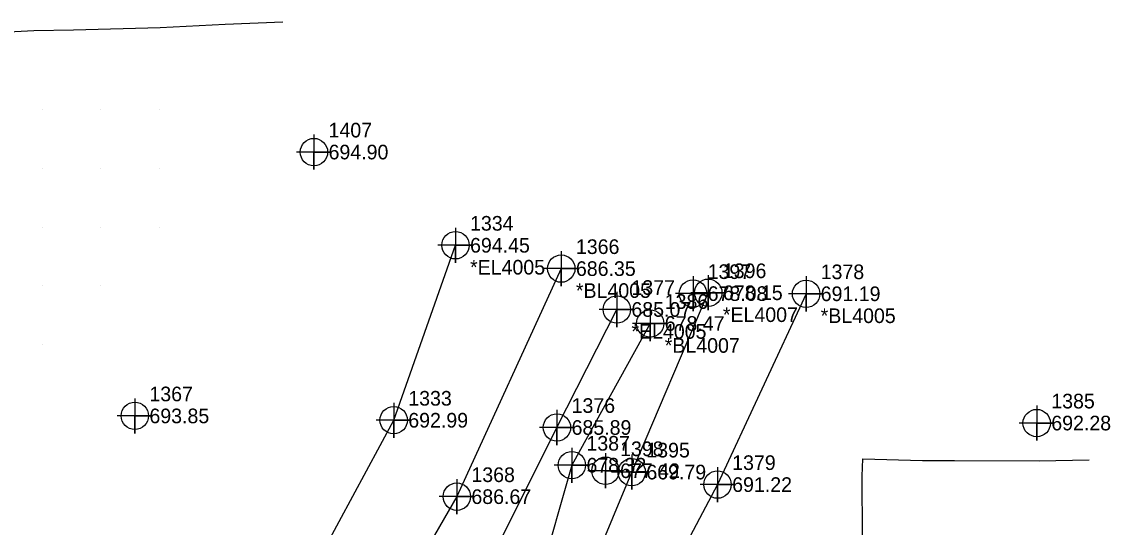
# Model space of a CAD drawing. Extents: x 1755643 to 1760494, y 736519 to 737621.
# Drawn here: x 1759022 to 1759208.1, y 737123.7 to 737210.1 of the extents above; entities that cross this region are included whole.
import ezdxf

# ---------------------------------------------------------------- set-up
doc = ezdxf.new("R2010")
doc.units = 0
for name, color, linetype in [('Exist Horizontal Alignment Curve and Spiral Data', 7, 'Continuous'), ('Exist Horizontal Alignment Direction Label', 7, 'Continuous'), ('Exist Railroads Standard Gauge', 7, 'Continuous'), ('Exist Roads EOT', 7, 'Continuous'), ('Exist Utilities Sanitary Sewer UG Line', 7, 'Continuous'), ('Old_Level_3', 7, 'Continuous'), ('Prop Conc 5in Monolithic Keyed In Island', 7, 'Continuous'), ('Prop EOT Dash', 7, 'Continuous'), ('Prop Horizontal Alignment Station Label', 7, 'Continuous'), ('Prop Horizontal Alignment Tick Label', 7, 'Continuous'), ('Prop Horizontal Alignment Tick Large', 7, 'Continuous'), ('Prop Horizontal Alignment Tick Small', 7, 'Continuous'), ('Prop Lane Lines', 7, 'Continuous'), ('Prop Paint Stripe', 7, 'Continuous'), ('Prop Paved Shoulder', 7, 'Continuous'), ('Prop Superelevation Label', 7, 'Continuous'), ('Prop Terminator CELL', 7, 'Continuous'), ('Scratch_Level_9', 7, 'Continuous')]:
    doc.layers.add(name, color=color, linetype=linetype)

msp = doc.modelspace()

# ---------------------------------------------------------------- linework, layer by layer
at = {"layer": 'Exist Horizontal Alignment Curve and Spiral Data'}
for points in [[(1759071.95, 737190.81), (1759071.95, 737184.81), (1759071.95, 737187.81), (1759074.95, 737187.81), (1759068.95, 737187.81)], [(1759041.32, 737145.72), (1759041.32, 737139.72), (1759041.32, 737142.72), (1759044.32, 737142.72), (1759038.32, 737142.72)], [(1759195.52, 737144.5), (1759195.52, 737138.5), (1759195.52, 737141.5), (1759198.52, 737141.5), (1759192.52, 737141.5)]]:
    msp.add_lwpolyline(points, dxfattribs=at)
for centre in [(1759071.95, 737187.81), (1759041.32, 737142.72), (1759195.52, 737141.5)]:
    msp.add_circle(centre, 2.34, dxfattribs=at)
at = {"layer": 'Exist Railroads Standard Gauge'}
for points in [[(1758963.25, 737206.56), (1758981.75, 737206.72), (1758990.89, 737207.08), (1759006.59, 737207.68), (1759024.04, 737208.6), (1759030.84, 737208.71), (1759045.64, 737209.09), (1759056.75, 737209.66), (1759066.65, 737210.07)], [(1759166.23, 737089.04), (1759166.56, 737104.02), (1759165.73, 737122.15), (1759165.69, 737132.45), (1759165.81, 737135.36), (1759176, 737135.12), (1759181.45, 737135.1), (1759195.95, 737135.05), (1759204.48, 737135.24)]]:
    msp.add_lwpolyline(points, dxfattribs=at)
at = {"layer": 'Prop Horizontal Alignment Station Label'}
for points in [[(1759136.76, 737166.62), (1759136.76, 737160.62), (1759136.76, 737163.62), (1759139.76, 737163.62), (1759133.76, 737163.62)], [(1759121.79, 737136.35), (1759121.79, 737130.35), (1759121.79, 737133.35), (1759124.79, 737133.35), (1759118.79, 737133.35)]]:
    msp.add_lwpolyline(points, dxfattribs=at)
for centre in [(1759136.76, 737163.62), (1759121.79, 737133.35)]:
    msp.add_circle(centre, 2.34, dxfattribs=at)
at = {"layer": 'Prop Horizontal Alignment Tick Small'}
for points in [[(1759139.37, 737166.77), (1759139.37, 737160.77), (1759139.37, 737163.77), (1759142.37, 737163.77), (1759136.37, 737163.77)], [(1759129.43, 737161.51), (1759129.43, 737155.51), (1759129.43, 737158.51), (1759132.43, 737158.51), (1759126.43, 737158.51)], [(1759116.04, 737137.29), (1759116.04, 737131.29), (1759116.04, 737134.29), (1759119.04, 737134.29), (1759113.04, 737134.29)], [(1759126.28, 737136.12), (1759126.28, 737130.12), (1759126.28, 737133.12), (1759129.28, 737133.12), (1759123.28, 737133.12)]]:
    msp.add_lwpolyline(points, dxfattribs=at)
for centre in [(1759139.37, 737163.77), (1759129.43, 737158.51), (1759116.04, 737134.29), (1759126.28, 737133.12)]:
    msp.add_circle(centre, 2.34, dxfattribs=at)
at = {"layer": 'Prop Lane Lines'}
for points in [[(1759096.14, 737174.88), (1759096.14, 737168.88), (1759096.14, 737171.88), (1759099.14, 737171.88), (1759093.14, 737171.88)], [(1759114.24, 737170.89), (1759114.24, 737164.89), (1759114.24, 737167.89), (1759117.24, 737167.89), (1759111.24, 737167.89)], [(1759156.09, 737166.59), (1759156.09, 737160.59), (1759156.09, 737163.59), (1759159.09, 737163.59), (1759153.09, 737163.59)], [(1759123.73, 737163.9), (1759123.73, 737157.9), (1759123.73, 737160.9), (1759126.73, 737160.9), (1759120.73, 737160.9)], [(1759085.58, 737144.98), (1759085.58, 737138.98), (1759085.58, 737141.98), (1759088.58, 737141.98), (1759082.58, 737141.98)], [(1759113.5, 737143.74), (1759113.5, 737137.74), (1759113.5, 737140.74), (1759116.5, 737140.74), (1759110.5, 737140.74)], [(1759140.96, 737133.98), (1759140.96, 737127.98), (1759140.96, 737130.98), (1759143.96, 737130.98), (1759137.96, 737130.98)], [(1759096.37, 737131.92), (1759096.37, 737125.92), (1759096.37, 737128.92), (1759099.37, 737128.92), (1759093.37, 737128.92)]]:
    msp.add_lwpolyline(points, dxfattribs=at)
for centre in [(1759096.14, 737171.88), (1759114.24, 737167.89), (1759156.09, 737163.59), (1759123.73, 737160.9), (1759085.58, 737141.98), (1759113.5, 737140.74), (1759140.96, 737130.98), (1759096.37, 737128.92)]:
    msp.add_circle(centre, 2.34, dxfattribs=at)
at = {"layer": 'Prop Paint Stripe'}
for p, q in [((1759025.51, 737195.01), (1759025.51, 737195.01)), ((1759035.51, 737195.01), (1759035.51, 737195.01)), ((1759045.51, 737195.01), (1759045.51, 737195.01)), ((1759025.51, 737185), (1759025.51, 737185)), ((1759035.51, 737185), (1759035.51, 737185)), ((1759045.51, 737185), (1759045.51, 737185)), ((1759025.51, 737175), (1759025.51, 737175)), ((1759035.51, 737175), (1759035.51, 737175)), ((1759045.51, 737175), (1759045.51, 737175)), ((1759025.51, 737165), (1759025.51, 737165)), ((1759035.51, 737165), (1759035.51, 737165)), ((1759025.51, 737155), (1759025.51, 737155)), ((1759205.53, 737145), (1759205.53, 737145))]:
    msp.add_line(p, q, dxfattribs=at)
at = {"layer": 'Prop Terminator CELL'}
for points in [[(1759091.13, 737054.23), (1759095.9, 737066.78), (1759106.11, 737092.63), (1759116.26, 737109.01), (1759126.28, 737133.12), (1759139.37, 737163.77)], [(1759129.43, 737158.51), (1759116.04, 737134.29), (1759110.5, 737114.91), (1759098.55, 737092.32), (1759085.82, 737054.03)]]:
    msp.add_lwpolyline(points, dxfattribs=at)
at = {"layer": 'Scratch_Level_9'}
for points in [[(1759028.25, 737064.28), (1759045.7, 737067.65), (1759061.18, 737092.69), (1759069.23, 737111.66), (1759085.58, 737141.98), (1759096.14, 737171.88)], [(1759114.24, 737167.89), (1759096.37, 737128.92), (1759076.67, 737094.82), (1759063.37, 737070.55), (1759053.4, 737057.9), (1759070.29, 737057.83), (1759078.13, 737065.6), (1759087.49, 737092.17), (1759101.52, 737116.77), (1759113.5, 737140.74), (1759123.73, 737160.9)], [(1759156.09, 737163.59), (1759140.96, 737130.98), (1759127.5, 737105.58), (1759120.62, 737081.6), (1759120.42, 737066.39), (1759121.45, 737059.32)]]:
    msp.add_lwpolyline(points, dxfattribs=at)

# ---------------------------------------------------------------- texts
at = {"layer": 'Exist Horizontal Alignment Direction Label'}
for s, p in [('*EL4005', (1759098.64, 737166.88)), ('*BL4005', (1759116.74, 737162.89)), ('*BL4005', (1759158.59, 737158.59)), ('*EL4005', (1759126.23, 737155.91))]:
    msp.add_text(s, height=2.5, dxfattribs=at).set_placement(p)
at = {"layer": 'Exist Roads EOT'}
for s, p in [('1407', (1759074.45, 737190.31)), ('1367', (1759043.82, 737145.22)), ('1385', (1759198.02, 737144))]:
    msp.add_text(s, height=2.5, dxfattribs=at).set_placement(p)
at = {"layer": 'Exist Utilities Sanitary Sewer UG Line'}
for s, p in [('678.15', (1759141.87, 737162.52)), ('678.47', (1759131.93, 737157.26)), ('678.32', (1759118.54, 737133.04)), ('669.79', (1759128.78, 737131.87))]:
    msp.add_text(s, height=2.5, dxfattribs=at).set_placement(p)
at = {"layer": 'Old_Level_3'}
for s, p in [('694.45', (1759098.64, 737170.63)), ('686.35', (1759116.74, 737166.64)), ('691.19', (1759158.59, 737162.34)), ('685.07', (1759126.23, 737159.66)), ('692.99', (1759088.08, 737140.73)), ('685.89', (1759116, 737139.49)), ('691.22', (1759143.46, 737129.73)), ('686.67', (1759098.87, 737127.67))]:
    msp.add_text(s, height=2.5, dxfattribs=at).set_placement(p)
at = {"layer": 'Prop Conc 5in Monolithic Keyed In Island'}
for s, p in [('1396', (1759141.87, 737166.27)), ('1386', (1759131.93, 737161.01)), ('1387', (1759118.54, 737136.79)), ('1395', (1759128.78, 737135.62))]:
    msp.add_text(s, height=2.5, dxfattribs=at).set_placement(p)
at = {"layer": 'Prop EOT Dash'}
for s, p in [('1334', (1759098.64, 737174.38)), ('1366', (1759116.74, 737170.39)), ('1378', (1759158.59, 737166.09)), ('1377', (1759126.23, 737163.41)), ('1333', (1759088.08, 737144.48)), ('1376', (1759116, 737143.24)), ('1379', (1759143.46, 737133.48)), ('1368', (1759098.87, 737131.42))]:
    msp.add_text(s, height=2.5, dxfattribs=at).set_placement(p)
at = {"layer": 'Prop Horizontal Alignment Tick Label'}
for s, p in [('1397', (1759139.26, 737166.12)), ('1398', (1759124.29, 737135.85))]:
    msp.add_text(s, height=2.5, dxfattribs=at).set_placement(p)
at = {"layer": 'Prop Horizontal Alignment Tick Large'}
for s, p in [('678.08', (1759139.26, 737162.37)), ('677.42', (1759124.29, 737132.1))]:
    msp.add_text(s, height=2.5, dxfattribs=at).set_placement(p)
at = {"layer": 'Prop Paved Shoulder'}
for s, p in [('694.90', (1759074.45, 737186.56)), ('693.85', (1759043.82, 737141.47)), ('692.28', (1759198.02, 737140.25))]:
    msp.add_text(s, height=2.5, dxfattribs=at).set_placement(p)
at = {"layer": 'Prop Superelevation Label'}
for s, p in [('*EL4007', (1759141.87, 737158.77)), ('*BL4007', (1759131.93, 737153.51))]:
    msp.add_text(s, height=2.5, dxfattribs=at).set_placement(p)

doc.saveas('drawing.dxf')
